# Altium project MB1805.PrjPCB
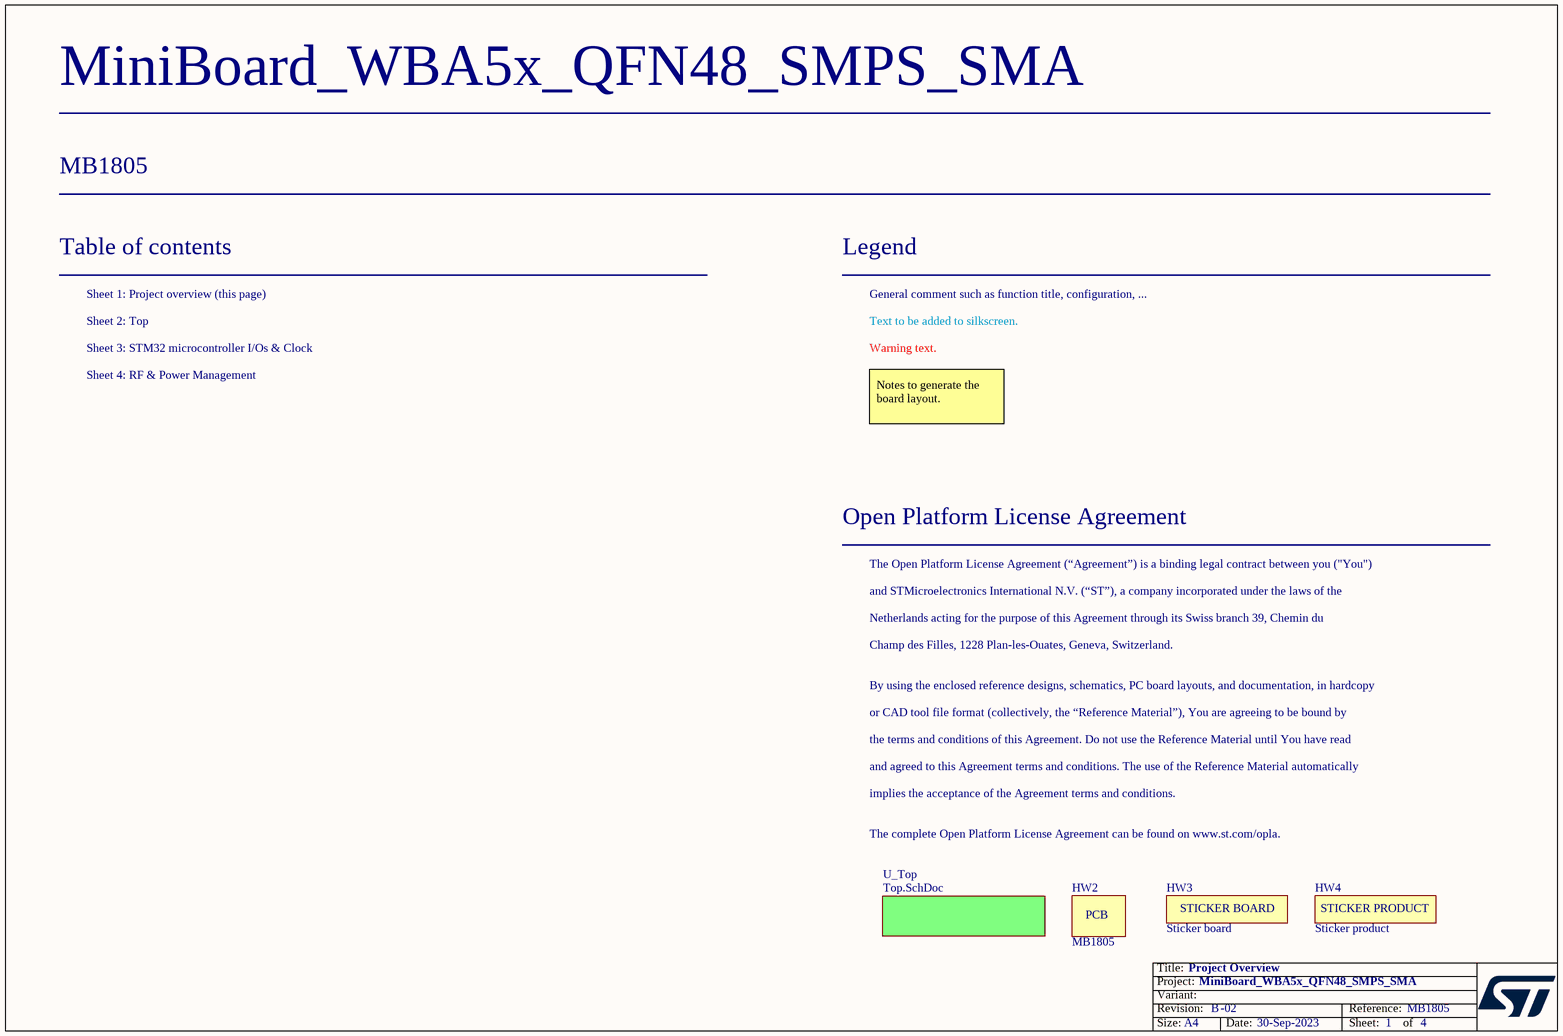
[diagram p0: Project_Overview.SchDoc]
Board_Assembly_Revision: 02; Board_Document_Date: 30-Sep-2023; Board_Name: MiniBoard_WBA5x_QFN48_SMPS_SMA; Board_PCB_Revision: B; Board_Reference: MB1805
4 sheets, 103 parts. Net scope: flat (ports and power ports of the same name join across sheets).
Board file: MB1805.PcbDoc
Sheets:
  Project_Overview.SchDoc
    U_Top = Top.SchDoc
      STM32 microcontroller I/Os & Clock = MCU.SchDoc
      RF & Power Management Schematic = RF&Power_Management.SchDoc

## Sheet Project_Overview.SchDoc: Project Overview
size A4; Date: Not used; ApprovedBy: Not used; CheckedBy: Not used; Author: Not used; CompanyName: STMicroelectronics; DrawnBy: Not used; Engineer: Not used; Organization: Not used; Address1: Not used; Address2: Not used; Address3: Not used; Address4: Not used; DocumentNumber: Not used; Revision: Not used; SheetNumber: 1; SheetTotal: 4

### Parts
HW2  value MB1805  (hidden comment: PCB)  (mechanical)
HW3  value Sticker board  [STICKER_BOARD_25X5]  (hidden comment: STICKER_BOARD)  (no BOM)
HW4  value Sticker product  [STICKER_PRODUCT_25X5]  (hidden comment: STICKER_PRODUCT)  (no BOM)

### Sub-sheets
U_Top = Top.SchDoc: no entries

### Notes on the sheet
- Table of contents
- Sheet 1: Project overview (this page)
- Legend
- General comment such as function title, configuration, ...
- Sheet 2: Top
- Sheet 3: STM32 microcontroller I/Os & Clock
- Sheet 4: RF & Power Management
- Text to be added to silkscreen.
- Warning text.
- Notes to generate the board layout.
- Open Platform License Agreement
- The Open Platform License Agreement (“Agreement”) is a binding legal contract between you ("You")
- and STMicroelectronics International N.V. (“ST”), a company incorporated under the laws of the
- Netherlands acting for the purpose of this Agreement through its Swiss branch 39, Chemin du
- Champ des Filles, 1228 Plan-les-Ouates, Geneva, Switzerland.
- By using the enclosed reference designs, schematics, PC board layouts, and documentation, in hardcopy
- or CAD tool file format (collectively, the “Reference Material”), You are agreeing to be bound by
- the terms and conditions of this Agreement. Do not use the Reference Material until You have read
- and agreed to this Agreement terms and conditions. The use of the Reference Material automatically
- implies the acceptance of the Agreement terms and conditions.
- The complete Open Platform License Agreement can be found on www.st.com/opla.

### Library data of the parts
HW2 = MCD-03003: PCB MB1805, 4L2S of MiniBoard for STM32WBA55, QFN48, SMPS, SMA.; Part_Preference: Recommended; Manufacturer: PLOTEC; ShowFields: YES; ID: 5119
HW3 = MCD-02190: Sticker board 25x5 mm; Part_Type: Misc; Part_Preference: Recommended
HW4 = MCD-02189: Sticker product 25x5 mm; Part_Type: Misc; Part_Preference: Recommended

## Sheet Top.SchDoc: Top Schematic
size A4; Date: Not used; ApprovedBy: Not used; CheckedBy: Not used; Author: Not used; CompanyName: STMicroelectronics; DrawnBy: Not used; Engineer: Not used; Organization: Not used; Address1: Not used; Address2: Not used; Address3: Not used; Address4: Not used; DocumentNumber: Not used; Revision: Not used; SheetNumber: 2; SheetTotal: 4
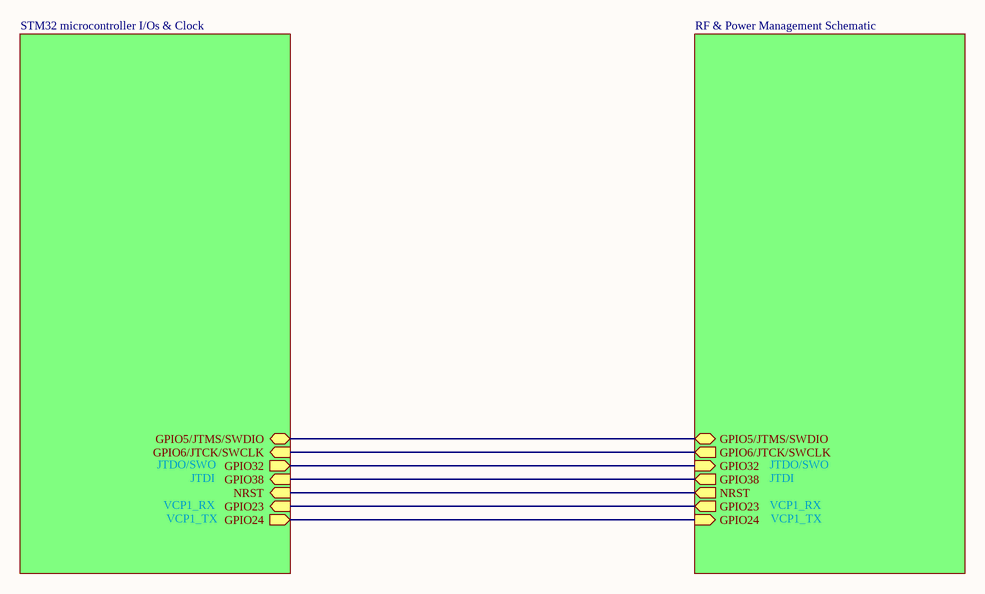
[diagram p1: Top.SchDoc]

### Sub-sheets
RF & Power Management Schematic = RF&Power_Management.SchDoc: GPIO5/JTMS/SWDIO (bidir), GPIO6/JTCK/SWCLK (out), GPIO32 (in), GPIO38 (out), NRST (out), GPIO23 (out), GPIO24 (in)
STM32 microcontroller I/Os & Clock = MCU.SchDoc: GPIO5/JTMS/SWDIO (bidir), GPIO6/JTCK/SWCLK (in), GPIO32 (out), GPIO38 (in), NRST (in), GPIO23 (in), GPIO24 (out)

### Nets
(unnamed): sheet STM32 microcontroller I/Os & Clock/GPIO5/JTMS/SWDIO, sheet RF & Power Management Schematic/GPIO5/JTMS/SWDIO
(unnamed): sheet STM32 microcontroller I/Os & Clock/GPIO6/JTCK/SWCLK, sheet RF & Power Management Schematic/GPIO6/JTCK/SWCLK  [a separate net that carries the same name]
(unnamed): sheet STM32 microcontroller I/Os & Clock/GPIO32, sheet RF & Power Management Schematic/GPIO32  [a separate net that carries the same name]
(unnamed): sheet STM32 microcontroller I/Os & Clock/GPIO38, sheet RF & Power Management Schematic/GPIO38  [a separate net that carries the same name]
(unnamed): sheet STM32 microcontroller I/Os & Clock/NRST, sheet RF & Power Management Schematic/NRST  [a separate net that carries the same name]
(unnamed): sheet STM32 microcontroller I/Os & Clock/GPIO23, sheet RF & Power Management Schematic/GPIO23  [a separate net that carries the same name]
(unnamed): sheet STM32 microcontroller I/Os & Clock/GPIO24, sheet RF & Power Management Schematic/GPIO24  [a separate net that carries the same name]

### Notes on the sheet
- JTDO/SWO
- VCP1_RX
- VCP1_TX
- JTDI

## Sheet MCU.SchDoc: STM32 microcontroller I/Os & Clock
size A4; Date: Not used; ApprovedBy: Not used; CheckedBy: Not used; Author: Not used; CompanyName: STMicroelectronics; DrawnBy: Not used; Engineer: Not used; Organization: Not used; Address1: Not used; Address2: Not used; Address3: Not used; Address4: Not used; DocumentNumber: Not used; Revision: Not used; SheetNumber: 3; SheetTotal: 4
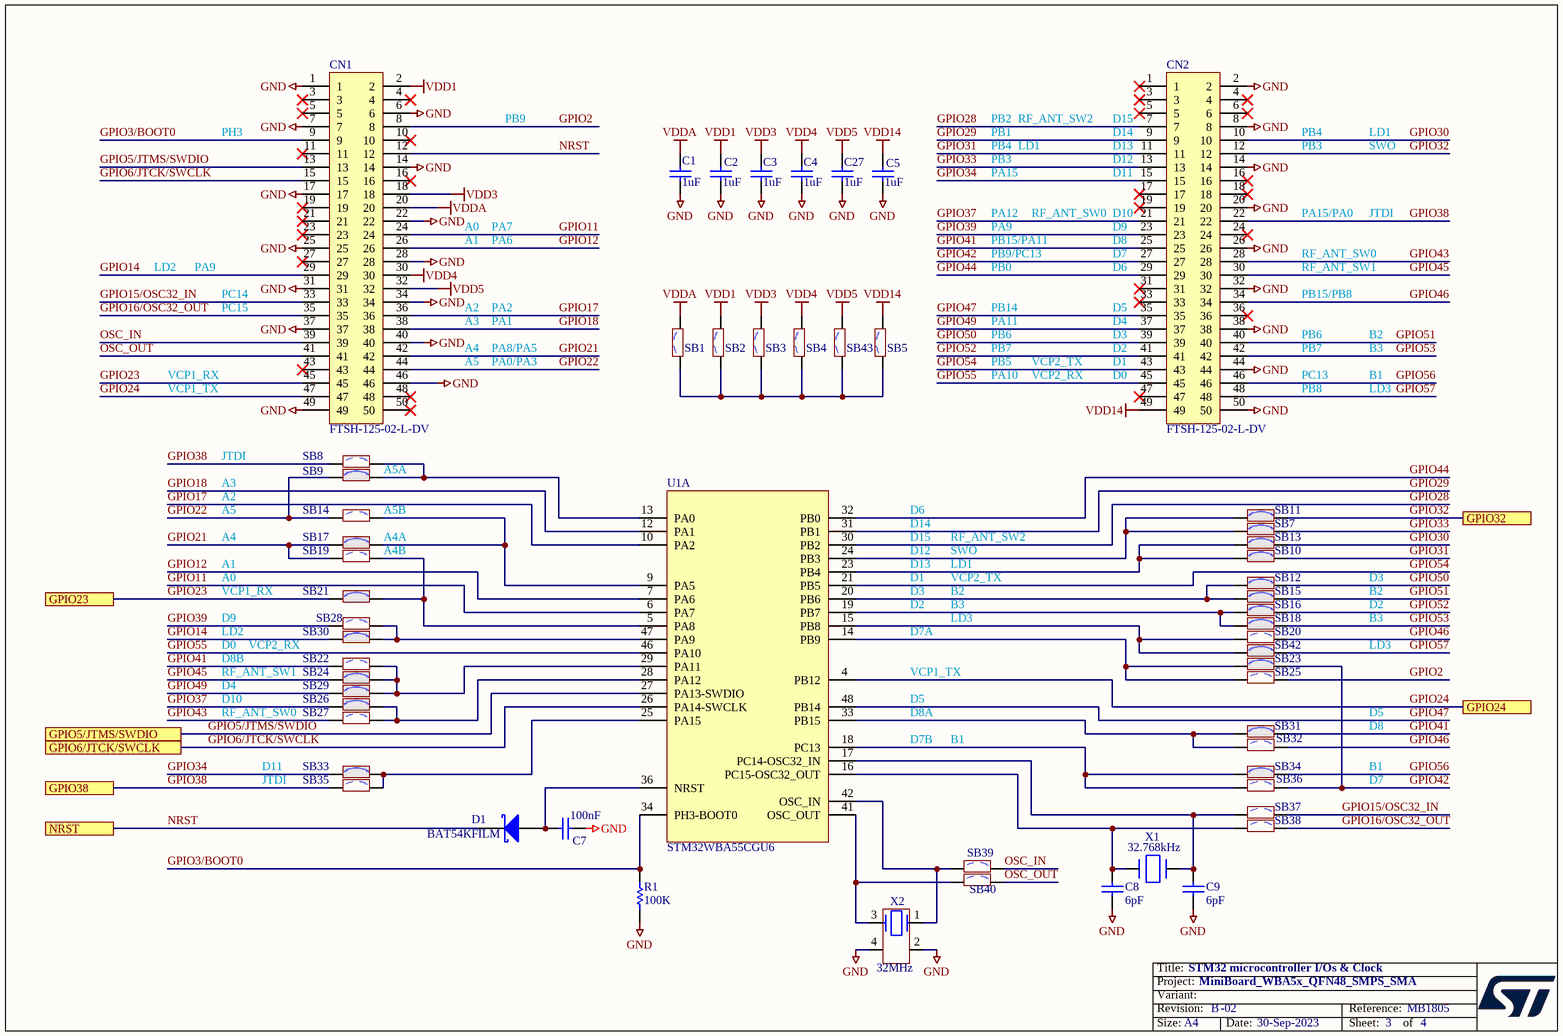
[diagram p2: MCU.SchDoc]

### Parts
C1  value 1uF  [C0402]  (hidden comment: Capacitor)
C2  value 1uF  [C0402]  (hidden comment: Capacitor)
C3  value 1uF  [C0402]  (hidden comment: Capacitor)
C4  value 1uF  [C0402]  (hidden comment: Capacitor)
C5  value 1uF  [C0402]  (hidden comment: Capacitor)
C7  value 100nF  [C0402]  (hidden comment: Capacitor)
C8  value 6pF  [C0402]  (hidden comment: Capacitor)
C9  value 6pF  [C0402]  (hidden comment: Capacitor)
C27  value 1uF  [C0402]  (hidden comment: Capacitor)
CN1  FTSH-125-02-L-DV  [FTSH-125-02-L-DV]
CN2  FTSH-125-02-L-DV  [FTSH-125-02-L-DV]
D1  value BAT54KFILM  [DIO_SOD523_1A_2K]  (hidden comment: SCHOTTKY_1A_2K)
R1  value 100K  [R0402]  (hidden comment: Resistor)
SB1  SB_OFF  [SOLDER-BRIDGE_R0402-0R]  (value not drawn)
SB2  SB_OFF  [SOLDER-BRIDGE_R0402-0R]  (value not drawn)
SB3  SB_OFF  [SOLDER-BRIDGE_R0402-0R]  (value not drawn)
SB4  SB_OFF  [SOLDER-BRIDGE_R0402-0R]  (value not drawn)
SB5  SB_OFF  [SOLDER-BRIDGE_R0402-0R]  (value not drawn)
SB7  SB_ON  [SOLDER-BRIDGE_R0402-0R]  (value not drawn)
SB8  SB_OFF  [SOLDER-BRIDGE_R0402-0R]  (value not drawn)
SB9  SB_ON  [SOLDER-BRIDGE_R0402-0R]  (value not drawn)
SB10  SB_ON  [SOLDER-BRIDGE_R0402-0R]  (value not drawn)
SB11  SB_ON  [SOLDER-BRIDGE_R0402-0R]  (value not drawn)
SB12  SB_ON  [SOLDER-BRIDGE_R0402-0R]  (value not drawn)
SB13  SB_ON  [SOLDER-BRIDGE_R0402-0R]  (value not drawn)
SB14  SB_OFF  [SOLDER-BRIDGE_R0402-0R]  (value not drawn)
SB15  SB_ON  [SOLDER-BRIDGE_R0402-0R]  (value not drawn)
SB16  SB_ON  [SOLDER-BRIDGE_R0402-0R]  (value not drawn)
SB17  SB_ON  [SOLDER-BRIDGE_R0402-0R]  (value not drawn)
SB18  SB_ON  [SOLDER-BRIDGE_R0402-0R]  (value not drawn)
SB19  SB_OFF  [SOLDER-BRIDGE_R0402-0R]  (value not drawn)
SB20  SB_OFF  [SOLDER-BRIDGE_R0402-0R]  (value not drawn)
SB21  SB_ON  [SOLDER-BRIDGE_R0402-0R]  (value not drawn)
SB22  SB_OFF  [SOLDER-BRIDGE_R0402-0R]  (value not drawn)
SB23  SB_ON  [SOLDER-BRIDGE_R0402-0R]  (value not drawn)
SB24  SB_ON  [SOLDER-BRIDGE_R0402-0R]  (value not drawn)
SB25  SB_OFF  [SOLDER-BRIDGE_R0402-0R]  (value not drawn)
SB26  SB_ON  [SOLDER-BRIDGE_R0402-0R]  (value not drawn)
SB27  SB_OFF  [SOLDER-BRIDGE_R0402-0R]  (value not drawn)
SB28  SB_OFF  [SOLDER-BRIDGE_R0402-0R]  (value not drawn)
SB29  SB_ON  [SOLDER-BRIDGE_R0402-0R]  (value not drawn)
SB30  SB_ON  [SOLDER-BRIDGE_R0402-0R]  (value not drawn)
SB31  SB_ON  [SOLDER-BRIDGE_R0402-0R]  (value not drawn)
SB32  SB_OFF  [SOLDER-BRIDGE_R0402-0R]  (value not drawn)
SB33  SB_ON  [SOLDER-BRIDGE_R0402-0R]  (value not drawn)
SB34  SB_ON  [SOLDER-BRIDGE_R0402-0R]  (value not drawn)
SB35  SB_OFF  [SOLDER-BRIDGE_R0402-0R]  (value not drawn)
SB36  SB_OFF  [SOLDER-BRIDGE_R0402-0R]  (value not drawn)
SB37  SB_OFF  [SOLDER-BRIDGE_R0402-0R]  (value not drawn)
SB38  SB_OFF  [SOLDER-BRIDGE_R0402-0R]  (value not drawn)
SB39  SB_OFF  [SOLDER-BRIDGE_R0402-0R]  (value not drawn)
SB40  SB_OFF  [SOLDER-BRIDGE_R0402-0R]  (value not drawn)
SB42  SB_ON  [SOLDER-BRIDGE_R0402-0R]  (value not drawn)
SB43  SB_OFF  [SOLDER-BRIDGE_R0402-0R]  (value not drawn)
U1  STM32WBA55CGU6  [ICC_UFQFPN48-EPAD_7X7_H0P55_P050]  (part A of 3)
X1  value 32.768kHz  [CRY_NX1610SE_2P]  (hidden comment: XTAL_2_PINS)
X2  value 32MHz  [CRY_NX1612SA_4P]  (hidden comment: XTAL_4_PINS)

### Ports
GPIO5/JTMS/SWDIO, GPIO6/JTCK/SWCLK, GPIO23, GPIO24, GPIO32, GPIO38, NRST

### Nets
GND: C1.1 C2.1 C3.1 C4.1 C5.1 C7.1 C8.1 C9.1 C27.1 CN1.1 CN1.6 CN1.7 CN1.14 CN1.17 CN1.22 CN1.25 CN1.28 CN1.31 CN1.34 CN1.37 CN1.40 CN1.46 CN1.49 CN2.2 CN2.8 CN2.14 CN2.20 CN2.26 CN2.32 CN2.38 CN2.44 CN2.50 R1.2 X2.2 X2.4
VDD1: C2.2 CN1.2 SB2.2
VDD3: C3.2 CN1.18 SB3.2
VDD4: C4.2 CN1.30 SB4.2
VDD5: C27.2 CN1.32 SB43.2
VDD14: C5.2 CN2.49 SB5.2
VDDA: C1.2 CN1.20 SB1.2
GPIO2: CN1.8 SB25.2
GPIO3/BOOT0: CN1.9 R1.1 U1.34(PH3-BOOT0)
GPIO5/JTMS/SWDIO: CN1.13 U1.27(PA13-SWDIO) ; port GPIO5/JTMS/SWDIO
GPIO6/JTCK/SWCLK: CN1.15 U1.26(PA14-SWCLK) ; port GPIO6/JTCK/SWCLK
GPIO11: CN1.24 U1.6(PA7)
GPIO12: CN1.26 U1.7(PA6)
GPIO14: CN1.29 SB30.1
GPIO15/OSC32_IN: CN1.33 SB37.2
GPIO16/OSC32_OUT: CN1.35 SB38.2
GPIO17: CN1.36 U1.10(PA2)
GPIO18: CN1.38 U1.12(PA1)
GPIO21: CN1.42 SB17.1 SB19.1
GPIO22: CN1.44 SB9.1 SB14.1
GPIO23: CN1.45 SB21.1 ; port GPIO23
GPIO24: CN1.47 U1.4(PB12) ; port GPIO24
GPIO28: CN2.7 U1.30(PB2)
GPIO29: CN2.9 U1.31(PB1)
GPIO30: CN2.10 SB13.2
GPIO31: CN2.11 SB10.2
GPIO32: CN2.12 SB11.2 ; port GPIO32
GPIO33: CN2.13 SB7.2
GPIO34: CN2.15 SB33.1
GPIO37: CN2.21 SB26.1
GPIO38: CN2.22 SB8.1 SB35.1 ; port GPIO38
GPIO39: CN2.23 SB28.1
GPIO41: CN2.25 SB22.1 SB31.2
GPIO42: CN2.27 SB23.2 SB36.2
GPIO43: CN2.28 SB27.1
GPIO44: CN2.29 U1.32(PB0)
GPIO45: CN2.30 SB24.1
GPIO46: CN2.34 SB20.2 SB32.2
GPIO47: CN2.35 U1.48(PB14)
GPIO49: CN2.37 SB29.1
GPIO50: CN2.39 SB12.2
GPIO51: CN2.40 SB15.2
GPIO52: CN2.41 SB16.2
GPIO53: CN2.42 SB18.2
GPIO54: CN2.43 U1.21(PB5)
GPIO55: CN2.45 U1.46(PA10)
GPIO56: CN2.46 SB34.2
GPIO57: CN2.48 SB42.2
NRST: CN1.12 D1.2(K) ; port NRST
OSC_IN: CN1.39 SB39.2
OSC_OUT: CN1.41 SB40.2
NetC7_2: C7.2 D1.1(A) U1.36(NRST)
NetC8_2: C8.2 SB38.1 U1.16(PC15-OSC32_OUT) X1.2(X2)
NetC9_2: C9.2 SB37.1 U1.17(PC14-OSC32_IN) X1.1(X1)
NetSB1_1: SB1.1 SB2.1 SB3.1 SB4.1 SB5.1 SB43.1
NetSB7_1: SB7.1 SB11.1 U1.24(PB3)
NetSB8_2: SB8.2 SB9.2 U1.13(PA0)
NetSB10_1: SB10.1 SB13.1 U1.23(PB4)
NetSB12_1: SB12.1 SB15.1 U1.20(PB6)
NetSB14_2: SB14.2 SB17.2 U1.9(PA5)
NetSB16_1: SB16.1 SB18.1 U1.19(PB7)
NetSB19_2: SB19.2 SB21.2 U1.5(PA8)
NetSB20_1: SB20.1 SB42.1 U1.15(PB8)
NetSB22_2: SB22.2 SB24.2 SB29.2 U1.29(PA11)
NetSB23_1: SB23.1 SB25.1 U1.14(PB9)
NetSB26_2: SB26.2 SB27.2 U1.28(PA12)
NetSB28_2: SB28.2 SB30.2 U1.47(PA9)
NetSB31_1: SB31.1 SB32.1 U1.33(PB15)
NetSB33_2: SB33.2 SB35.2 U1.25(PA15)
NetSB34_1: SB34.1 SB36.1 U1.18(PC13)
NetSB39_1: SB39.1 U1.42(OSC_IN) X2.1
NetSB40_1: SB40.1 U1.41(OSC_OUT) X2.3

Not connected (* = marked no-connect by the designer): CN1 3* 4* 5* 10* 11* 16* 19* 21* 23* 27* 43* 48* 50*; CN2 1* 3* 4* 5* 6* 16* 17* 18* 19* 24* 31* 33* 36* 47*

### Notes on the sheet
- PH3
- PB9
- PB1
- PB2
- PB3
- PB4
- PA15
- LD1
- RF_ANT_SW2
- (near CN2) D11
- (near CN2) D13
- (near CN2) D14
- (near CN2) D15
- (near CN2) D12
- SWO
- A0
- A1
- PA6
- PA7
- PA9
- PB15/PA11
- PA12
- RF_ANT_SW0
- (near CN2) D10
- (near CN2) D9
- (near CN2) D8
- PA15/PA0
- JTDI
- LD2
- PC14
- PC15
- A2
- PA2
- PB14
- PB0
- PB9/PC13
- (near CN2) D7
- (near CN2) D6
- (near CN2) D5
- RF_ANT_SW1
- PB15/PB8
- VCP1_RX
- A5
- A4
- A3
- PA0/PA3
- PA8/PA5
- PA1
- PA11
- PA10
- PB5
- PB6
- PB7
- VCP2_TX
- VCP2_RX
- (near CN2) D1
- (near CN2) D4
- (near CN2) D3
- (near CN2) D2
- (near CN2) D0
- PC13
- B1
- B2
- B3
- VCP1_TX
- PB8
- LD3
- A5A
- (near SB14) A5B
- D6
- A4B
- A4A
- D12
- D1
- D13
- D15
- D14
- D3
- D0
- D9
- D7A
- D2
- D10
- D8B
- D4
- D8A
- D5
- D11
- D7B
- D7
- D8

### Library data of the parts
C1-C5 C27 = MCD-01722: Capacitor, MLCC, 1uF, 10V, X5R, +/-10%, 0402, T=0.5mm; Part_Preference: Recommended; Manufacturer: YAGEO; Manufacturer_Part_Number: CC0402KRX5R6BB105; Component_Country_Of_Origin: China
C7 = MCD-00006: Capacitor, MLCC, 100nF, 16V, X7R, +/-10%, 0402, T=0.5mm; Manufacturer_Part_Number: CC0402KRX7R7BB104; Manufacturer: YAGEO; Alternate_Manufacturer_Part_Number: GCM155R71C104KA55D; Alternate_Manufacturer: MURATA; Part_Preference: Recommended; Order_Code_RS: 616-9701
C8 C9 = MCD-03185: Capacitor, MLCC, 6 pF, 50V, NPO, ±0,25pF, 0402, T=0.5mm; Part_Preference: Recommended; Manufacturer: MURATA; Manufacturer_Part_Number: GJM1555C1H6R0CB01; Order_Code_RS: 170-6040; ShowFields: YES; ID: 5301
CN1 CN2 = MCD-02746: Header, 25x2, 12.7mm, VR, SMD, T=4.83mm; Part_Type: Connector; Part_Preference: Recommended; Manufacturer: SAMTEC; Value: Header 25x2; Component_Country_Of_Origin: China, Costa Rica, Malaysia, USA, Vietnam; ShowFields: YES; ID: 4858
D1 = MCD-01677: Small signal Schottky diodes; Part_Type: Diode; Manufacturer: STMICROELECTRONICS; BMS_Part_Number: 9151123; Part_Preference: Recommended; Manufacturer_HQ_COO: EU
R1 = MCD-00059: Resistor, 100K, 0402, +/-1%, 1/16W; Part_Preference: Recommended; Manufacturer: YAGEO; Manufacturer_Part_Number: RC0402FR-07100KL; Component_Country_Of_Origin: China
SB1-SB5 SB8 SB14 SB19 SB20 SB22 SB25 SB27 SB28 SB32 SB35-SB40 SB43 = MCD-02162: Solder Bridge 0402 OFF; Part_Type: Misc; Part_Preference: Recommended; Manufacturer: YAGEO; Manufacturer_Part_Number: RC0402JR-070RL; Order_Code_RS: 618-5804; Component_Country_Of_Origin: China
SB7 SB9-SB13 SB15-SB18 SB21 SB23 SB24 SB26 SB29-SB31 SB33 SB34 SB42 = MCD-01618: Solder Bridge 0402 ON; Part_Type: Misc; Part_Preference: Recommended; Manufacturer: YAGEO; Manufacturer_Part_Number: RC0402JR-070RL; Order_Code_RS: 618-5804; Component_Country_Of_Origin: China
U1 = MCD-02743: MCU, ARM Cortex-M33 32-bit, 1MB Flash, 128KB SRAM, With Crypto, SMPS; Part_Type: IC; Part_Preference: Recommended; Manufacturer: STMICROELECTRONICS; Order_Code_RS: 151-766; Component_Country_Of_Origin: China; ShowFields: YES; ID: 4855
X1 = MCD-02579: Crystal, 32.768kHz, 6pF, +/-20ppm, 70KR, 1.6x1mm; Part_Type: Crystal_Osc; Part_Preference: Recommended; Manufacturer: NDK; Manufacturer_Part_Number: NX1610SE-32.768KHZ-EXS00A-MU01501
X2 = MCD-02578: Crystal, 32MHz, 8pF, +/-10ppm, 40R, 1612(metric), T=0.3mm; Part_Type: Crystal_Osc; Part_Preference: Recommended; Manufacturer: NDK; Manufacturer_Part_Number: NX1612SA-32MHZ-EXS00A-CS09166

## Sheet RF&Power_Management.SchDoc: RF & Power Management Schematic
size A4; Date: Not used; ApprovedBy: Not used; CheckedBy: Not used; Author: Not used; CompanyName: STMicroelectronics; DrawnBy: Not used; Engineer: Not used; Organization: Not used; Address1: Not used; Address2: Not used; Address3: Not used; Address4: Not used; DocumentNumber: Not used; Revision: Not used; SheetNumber: 4; SheetTotal: 4
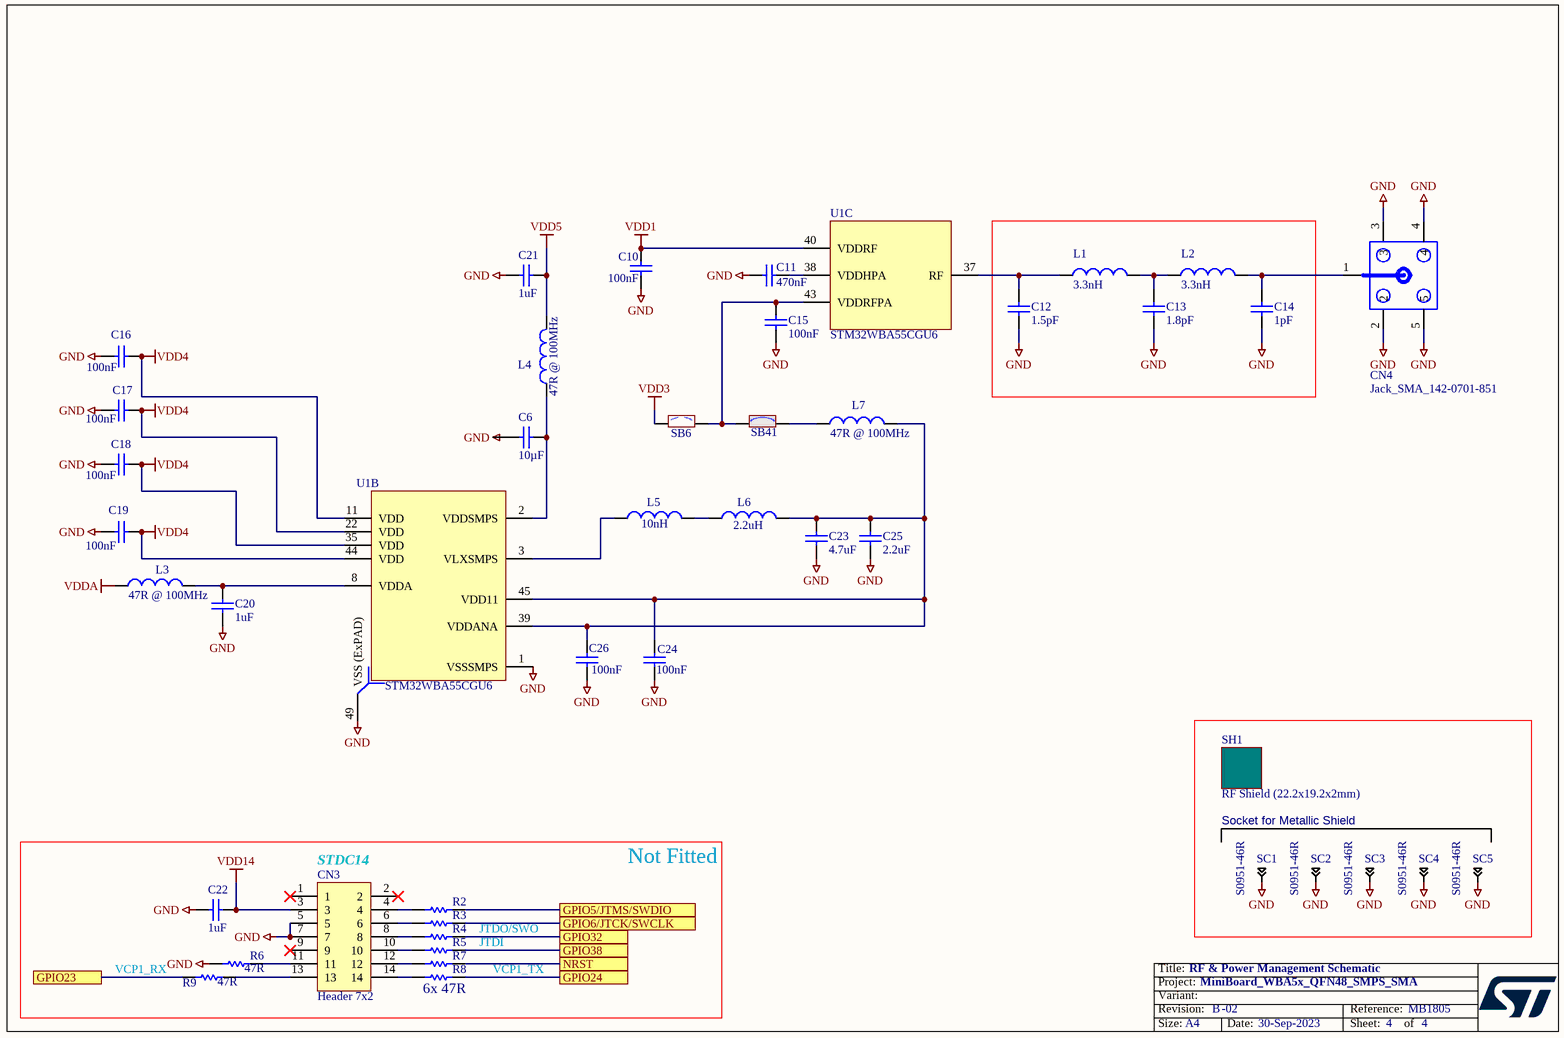
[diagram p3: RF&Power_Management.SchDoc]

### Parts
C6  value 10µF  [C0603_H0P8]  (hidden comment: Capacitor)
C10  value 100nF  [C0402]  (hidden comment: Capacitor)
C11  value 470nF  [C0603]  (hidden comment: Capacitor)
C12  value 1.5pF  [C0402]  (hidden comment: Capacitor)
C13  value 1.8pF  [C0402]  (hidden comment: Capacitor)
C14  value 1pF  [C0402]  (hidden comment: Capacitor)
C15  value 100nF  [C0402]  (hidden comment: Capacitor)
C16  value 100nF  [C0402]  (hidden comment: Capacitor)
C17  value 100nF  [C0402]  (hidden comment: Capacitor)
C18  value 100nF  [C0402]  (hidden comment: Capacitor)
C19  value 100nF  [C0402]  (hidden comment: Capacitor)
C20  value 1uF  [C0402]  (hidden comment: Capacitor)
C21  value 1uF  [C0402]  (hidden comment: Capacitor)
C22  value 1uF  [C0603]  (hidden comment: Capacitor)
C23  value 4.7uF  [C0402]  (hidden comment: Capacitor)
C24  value 100nF  [C0402]  (hidden comment: Capacitor)
C25  value 2.2uF  [C0402]  (hidden comment: Capacitor)
C26  value 100nF  [C0402]  (hidden comment: Capacitor)
CN3  Header 7x2  [CON_SAMTEC_FTSH-107-01-L-DV-K-A]
CN4  value Jack_SMA_142-0701-851  [CON_SMA-RF_CINCH_142-0701-851]  (hidden comment: mmcx)
L1  value 3.3nH  [C0402]  (hidden comment: Inductor)
L2  value 3.3nH  [C0402]  (hidden comment: Inductor)
L3  value 47R @ 100MHz  [IND_0603_H0P8]  (hidden comment: Inductor)
L4  value 47R @ 100MHz  [IND_0603_H0P8]  (hidden comment: Inductor)
L5  value 10nH  [C0402]  (hidden comment: Inductor)
L6  value 2.2uH  [L0805_H0P9]  (hidden comment: Inductor)
L7  value 47R @ 100MHz  [IND_0603_H0P8]  (hidden comment: Inductor)
R2  Resistor  [R0402]  (value not drawn)
R3  Resistor  [R0402]  (value not drawn)
R4  Resistor  [R0402]  (value not drawn)
R5  Resistor  [R0402]  (value not drawn)
R6  value 47R  [R0402]  (hidden comment: Resistor)
R7  Resistor  [R0402]  (value not drawn)
R8  Resistor  [R0402]  (value not drawn)
R9  value 47R  [R0402]  (hidden comment: Resistor)
SB6  SB_OFF  [SOLDER-BRIDGE_R0402-0R]  (value not drawn)
SB41  SB_ON  [SOLDER-BRIDGE_R0402-0R]  (value not drawn)
SC1  value S0951-46R  [CLIP_HARWIN_S0951-46R]  (hidden comment: Shield-clip_S0951-46R)
SC2  value S0951-46R  [CLIP_HARWIN_S0951-46R]  (hidden comment: Shield-clip_S0951-46R)
SC3  value S0951-46R  [CLIP_HARWIN_S0951-46R]  (hidden comment: Shield-clip_S0951-46R)
SC4  value S0951-46R  [CLIP_HARWIN_S0951-46R]  (hidden comment: Shield-clip_S0951-46R)
SC5  value S0951-46R  [CLIP_HARWIN_S0951-46R]  (hidden comment: Shield-clip_S0951-46R)
SH1  RF Shield (22.2x19.2x2mm)  [SHIELD_RF_ST-CUSTOM_22P2X19P2_H2]
U1  STM32WBA55CGU6  [ICC_UFQFPN48-EPAD_7X7_H0P55_P050]  (parts B,C of 3)

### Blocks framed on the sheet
Socket for Metallic Shield: SC1-SC5 SH1
Not Fitted: C22 CN3 R2-R9

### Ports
GPIO5/JTMS/SWDIO, GPIO6/JTCK/SWCLK, GPIO23, GPIO24, GPIO32, GPIO38, NRST

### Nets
GND: C6.2 C10.2 C11.1 C12.1 C13.1 C14.1 C15.2 C16.2 C17.2 C18.2 C19.2 C20.1 C21.2 C22.1 C23.1 C24.2 C25.2 C26.2 CN3.5 CN3.7 CN4.2 CN4.3 CN4.4 CN4.5 R6.1 SC1.1 SC2.1 SC3.1 SC4.1 SC5.1 U1.1(VSSSMPS) U1.49(VSS_(ExPAD))
VDD1: C10.1 U1.40(VDDRF)
VDD3: SB6.1
VDD4: C16.1 C17.1 C18.1 C19.1 U1.11(VDD) U1.22(VDD) U1.35(VDD) U1.44(VDD)
VDD5: C21.1 L4.2
VDD14: C22.2 CN3.3
VDDA: L3.1
GPIO5/JTMS/SWDIO: R2.2 ; port GPIO5/JTMS/SWDIO
GPIO6/JTCK/SWCLK: R3.2 ; port GPIO6/JTCK/SWCLK
GPIO23: R9.1 ; port GPIO23
GPIO24: R8.2 ; port GPIO24
GPIO32: R4.2 ; port GPIO32
GPIO38: R5.2 ; port GPIO38
NRST: R7.2 ; port NRST
NetC6_1: C6.1 L4.1 U1.2(VDDSMPS)
NetC11_2: C11.2 U1.38(VDDHPA)
NetC12_2: C12.2 L1.1 U1.37(RF)
NetC13_2: C13.2 L1.2 L2.1
NetC14_2: C14.2 CN4.1 L2.2
NetC15_1: C15.1 SB6.2 SB41.1 U1.43(VDDRFPA)
NetC20_2: C20.2 L3.2 U1.8(VDDA)
NetC23_2: C23.2 C24.1 C25.1 C26.1 L6.2 L7.2 U1.39(VDDANA) U1.45(VDD11)
NetCN3_4: CN3.4 R2.1
NetCN3_6: CN3.6 R3.1
NetCN3_8: CN3.8 R4.1
NetCN3_10: CN3.10 R5.1
NetCN3_11: CN3.11 R6.2
NetCN3_12: CN3.12 R7.1
NetCN3_13: CN3.13 R9.2
NetCN3_14: CN3.14 R8.1
NetL5_1: L5.1 U1.3(VLXSMPS)
NetL5_2: L5.2 L6.1
NetL7_1: L7.1 SB41.2

Not connected (* = marked no-connect by the designer): CN3 1* 2* 9*

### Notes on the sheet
- (near CN3) STDC14
- (near R9) VCP1_RX
- JTDI
- JTDO/SWO
- VCP1_TX
- (near R8) 6x 47R

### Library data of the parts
C6 = MCD-02733: Capacitor, MLCC, 10uF, 10V, X6S, +/-20%, 0603, T=1mm; Part_Preference: Recommended; Manufacturer: MURATA; Manufacturer_Part_Number: GRM188C81A106MA73; Order_Code_RS: 170-6242; Component_Country_Of_Origin: Japan; ShowFields: YES; ID: 4845
C10 C15-C19 C24 C26 = MCD-00006: as C7 on sheet MCU
C11 = MCD-01006: Capacitor, MLCC, 470nF, 16V, X7R, +/-10%, 0603, T=0.8mm; BMS_Part_Number: 9142003; Part_Preference: Recommended; Manufacturer: YAGEO; Manufacturer_Part_Number: CC0603KRX7R7BB474; Order_Code_RS: 200-6576; Component_Country_Of_Origin: China
C12 = MCD-02994: Capacitor, MLCC, 1.5pF, 50V, C0G, +/-0.25pF, 0402, T=0.5mm; Part_Preference: Recommended; Manufacturer: MURATA; Manufacturer_Part_Number: GRM1555C1H1R5CA01; Component_Country_Of_Origin: Japan°; ShowFields: YES; ID: 5110
C13 = MCD-02995: Capacitor, MLCC, 1.8pF, 50V, C0G, +/-0.25pF, 0402, T=0.5mm; Part_Preference: Recommended; Manufacturer: MURATA; Manufacturer_Part_Number: GRM1555C1H1R8CA01; Order_Code_RS: 723-5357; Component_Country_Of_Origin: Japan°; ShowFields: YES; ID: 5111
C14 = MCD-03045: Capacitor, MLCC, 1.0pF, 50V, C0G, +/-0.25pF, 0402, T=0.5mm; Part_Preference: Recommended; Manufacturer: MURATA; Manufacturer_Part_Number: GRM1555C1H1R0CA01; Component_Country_Of_Origin: China, Japan; ShowFields: YES; ID: 5161
C20 C21 = MCD-01722: as C1 on sheet MCU
C22 = MCD-00010: Capacitor, MLCC, 1uF, 16V, X5R, 10%, 0603, T=0,8mm; Manufacturer_Part_Number: CC0603KRX5R7BB105; Manufacturer: YAGEO; Provided_By: Subcon; Initial_Board_Reference: MB1274
C23 = MCD-01356: Capacitor, MLCC, 4.7uF, 6V3, X5R, +/-20%, 0402, T=0.5mm; Part_Preference: Recommended; Manufacturer: MURATA; Manufacturer_Part_Number: GRM155R60J475ME47; Order_Code_RS: 814-5230; Component_Country_Of_Origin: Japan; ShowFields: YES; ID: 3456
C25 = MCD-01823: Capacitor, MLCC, 2.2uF, 6V3, X5R,+/-10%, 0402, T=0.5mm; Part_Preference: Recommended; Manufacturer: MURATA; Manufacturer_Part_Number: GRM155R60J225KE95D; Order_Code_RS: 172-6478; Component_Country_Of_Origin: Japan; ShowFields: YES; ID: 3923
CN3 = MCD-01531: Header, 7x2, 1.27mm, VR, T=5.97mm, FTSH series STDC14 without Alignment Pin; Part_Type: Connector; Part_Preference: Recommended; Manufacturer: SAMTEC; Manufacturer_Part_Number: FTSH-107-01-L-DV-K; Order_Code_RS: 179-9021; Component_Country_Of_Origin: China, Costa Rica, Malaysia, United States, Vietnam
CN4 = MCD-02072: Jack_SMA, VR, PCB edge, 50R, T=7.92mm; Part_Type: Connector; Part_Preference: Recommended; Manufacturer: CINCH; Manufacturer_Part_Number: 142-0701-851; Order_Code_RS: 885-7532; Component_Country_Of_Origin: United States; ShowFields: YES; ID: 4172
L1 L2 = MCD-03001: Inductor, 3.3nH, +/-0.3nH, 0.8A,125mR, 0402, T=0.5mm; Part_Preference: Recommended; Manufacturer: MURATA; Manufacturer_Part_Number: LQG15HS3N3S02; Component_Country_Of_Origin: Japan°; ShowFields: YES; ID: 5117
L3 L4 L7 = MCD-02587: Ferrite bead, 47R @ 100MHz, +/-25%, 3.5A, 0R02, 0603, T=0.8mm; Part_Preference: Recommended; Manufacturer: TAIYO YUDEN; Manufacturer_Part_Number: FBMH1608HM470-T
L5 = MCD-03035: Inductor, 10nH, +/-2%, 500 mA, 0.26Ohm, 0402, T=0.5mm; Part_Preference: Recommended; Manufacturer: MURATA; Manufacturer_Part_Number: LQG15HS10NJ02D; Order_Code_RS: 124-8162; ShowFields: YES; ID: 5151
L6 = MCD-01060: Inductor, 2.2uH, +/-20%, 0.7A, 0R156, 0805, T=0.9mm; Part_Preference: Recommended; Manufacturer: MURATA; Manufacturer_Part_Number: LQM21PN2R2MGH; Order_Code_RS: 166-9883
R2-R9 = MCD-00481: Resistor,47R,0402,1%,1/16W; Manufacturer_Part_Number: RC0402FR-0747RL; Manufacturer: YAGEO; Provided_By: Subcon
SB6 = MCD-02162: as SB1 on sheet MCU
SB41 = MCD-01618: as SB7 on sheet MCU
SC1-SC5 = MCD-01587: shield clip Harwin S0951-46R to fix RF shielded cavity; Part_Type: Misc; Part_Preference: Recommended; Component_Country_Of_Origin: South Korea
SH1 = MCD-03256: Part_Type: Misc; Part_Preference: Recommended; Manufacturer: TBD; ShowFields: YES; ID: 5372
U1 = MCD-02743: as U1 on sheet MCU

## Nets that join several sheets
GND: MCU (35 pins), RF&Power_Management (32 pins)
VDD1: MCU (C2.2 CN1.2 SB2.2), RF&Power_Management (C10.1 U1.40)
VDD3: MCU (C3.2 CN1.18 SB3.2), RF&Power_Management (SB6.1)
VDD4: MCU (C4.2 CN1.30 SB4.2), RF&Power_Management (8 pins)
VDD5: MCU (C27.2 CN1.32 SB43.2), RF&Power_Management (C21.1 L4.2)
VDD14: MCU (C5.2 CN2.49 SB5.2), RF&Power_Management (C22.2 CN3.3)
VDDA: MCU (C1.2 CN1.20 SB1.2), RF&Power_Management (L3.1)
GPIO5/JTMS/SWDIO: MCU (CN1.13 U1.27), RF&Power_Management (R2.2)
GPIO6/JTCK/SWCLK: MCU (CN1.15 U1.26), RF&Power_Management (R3.2)
GPIO23: MCU (CN1.45 SB21.1), RF&Power_Management (R9.1)
GPIO24: MCU (CN1.47 U1.4), RF&Power_Management (R8.2)
GPIO32: MCU (CN2.12 SB11.2), RF&Power_Management (R4.2)
GPIO38: MCU (CN2.22 SB8.1 SB35.1), RF&Power_Management (R5.2)
NRST: MCU (CN1.12 D1.2), RF&Power_Management (R7.2)

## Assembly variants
WBA55CGB: not fitted C1 C2 C3 C4 C5 C22 C25 C27 CN3 R2 R3 R4 R5 R6 R7 R8 R9 SB1 SB2 SB3 SB4 SB5 SB6 SB8 SB14 SB19 SB20 SB22 SB25 SB27 SB28 SB32 SB35 SB36 SB37 SB38 SB39 SB40 SB43
no_SoC: not fitted C1 C2 C3 C4 C5 C22 C25 C27 CN3 R2 R3 R4 R5 R6 R7 R8 R9 SB1 SB2 SB3 SB4 SB5 SB6 SB8 SB14 SB19 SB20 SB22 SB25 SB27 SB28 SB32 SB35 SB36 SB37 SB38 SB39 SB40 SB43 U1 U1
